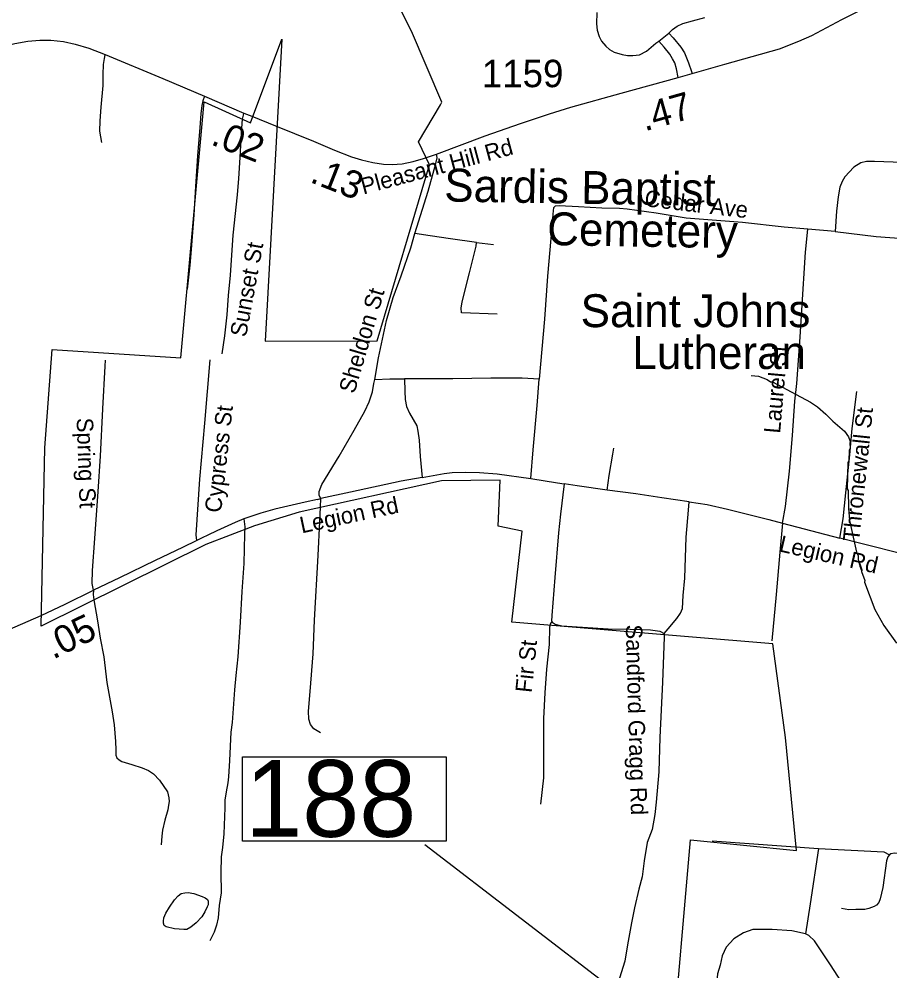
# Model space of a CAD drawing. Extents: x 1159738 to 1321356, y 736314 to 882035.
# Drawn here: x 1254810 to 1258783, y 771364 to 775705 of the extents above; entities that cross this region are included whole.
import ezdxf

# ---------------------------------------------------------------- set-up
doc = ezdxf.new("R2010")
doc.units = 0
for name, color, linetype in [('Exist Boundary Political City Limit New', 7, 'Continuous'), ('Exist Cultural Cemetery Label', 7, 'Continuous'), ('Exist Cultural Church Label', 7, 'Continuous'), ('Exist Hydrographic Misc Water Feature', 7, 'Continuous'), ('Exist Road Non-System Type 51', 7, 'Continuous'), ('Exist Road Non-System Type 51 Label', 7, 'Continuous'), ('Exist Road Secondary Mileage Hundredths English Label', 7, 'Continuous'), ('Exist Road Secondary Structure Standard Bridge Number Label', 7, 'Continuous'), ('Exist Road Secondary Type 51 Attributed', 7, 'Continuous'), ('Exist Road Secondary Type 51 Label', 7, 'Continuous'), ('Exist Road Secondary Type 51 Number Label', 7, 'Continuous'), ('Map Preparation Boundary City Limit Buffer Line', 7, 'Continuous')]:
    doc.layers.add(name, color=color, linetype=linetype)

msp = doc.modelspace()

# ---------------------------------------------------------------- linework, layer by layer
at = {"layer": 'Exist Boundary Political City Limit New'}
msp.add_line((1258356, 771913.3), (1258306.9, 772428.7), dxfattribs=at)
for points in [[(1256599.9, 775650.6), (1256435.6, 775978.4)], [(1254928, 773749.2), (1254960.4, 774198), (1255548.5, 774159.7), (1255654.5, 775328.1), (1255865.9, 775232.8), (1256009.3, 775613.5), (1255932.4, 774237), (1256443.1, 774237.4), (1256682.7, 775040.9), (1256632.8, 775144.8), (1256731.8, 775314.1), (1256738, 775325.9), (1256599.9, 775650.6)], [(1258306.9, 772428.7), (1258249, 772856.6), (1257057.6, 772954.5), (1257104.7, 773369.5), (1256995.9, 773393), (1257004.7, 773602), (1256737.1, 773599), (1256087.2, 773456.8), (1255884.4, 773394.8), (1255661.5, 773309.4), (1254910.4, 772936.9), (1254928, 773749.2)], [(1258748, 769032.9), (1258230, 768945), (1258209.5, 769082.6), (1258189.3, 769147.7), (1258154.9, 769175.3), (1258128.7, 769211), (1257960, 769313.2), (1257938.6, 769347.1), (1257845.4, 769353.7), (1257825.2, 769206.1), (1257207.5, 769215.7), (1257198, 769092), (1256982.3, 769096.7), (1257045.5, 769806.9), (1257710.9, 769757), (1257786.5, 770964.5), (1257872.3, 771962.7), (1258356, 771913.3)]]:
    msp.add_lwpolyline(points, dxfattribs=at)
at = {"layer": 'Exist Hydrographic Misc Water Feature'}
for points in [[(1258149.1, 774079.2), (1258183, 774076.1), (1258222.8, 774061.3), (1258238.4, 774050.3), (1258246.4, 774050.2), (1258420.1, 773958.1), (1258451.6, 773936.9), (1258490.8, 773904.1), (1258522, 773871.5), (1258574.8, 773826.1), (1258594.2, 773799.5), (1258601.6, 773778.8), (1258599.5, 773771.5), (1258600.9, 773746.8), (1258596.7, 773739.5), (1258595.4, 773691.1), (1258591.1, 773683), (1258588.1, 773563.2), (1258591.8, 773554.9), (1258593.8, 773475.3), (1258598.4, 773418.6), (1258630.7, 773274.3), (1258638.3, 773257.8), (1258637.8, 773242.2), (1258645, 773210), (1258652.6, 773193.5), (1258652.3, 773185.3), (1258667.4, 773144.8), (1258667.2, 773137.4), (1258714, 773013.3), (1258754.1, 772940.3), (1258812.1, 772858.7)], [(1255496.1, 771654.9), (1255518.9, 771688.1), (1255535.4, 771707.5), (1255549.6, 771717), (1255565.8, 771720.8), (1255581.9, 771722.1), (1255607.7, 771717.5), (1255645.3, 771704.4), (1255659.2, 771698.4), (1255669, 771690), (1255672.8, 771681.8), (1255672.7, 771676), (1255672.4, 771666.2), (1255668.2, 771656.4), (1255657.6, 771634.4), (1255643, 771610.9), (1255618.3, 771583.5), (1255593.8, 771564.3), (1255575.5, 771554), (1255561.4, 771552.7), (1255519.5, 771556), (1255481.7, 771564.9), (1255471.8, 771570.9), (1255468.2, 771581.6), (1255468.3, 771591.5), (1255470.8, 771607), (1255479.4, 771627.4), (1255496.1, 771654.9)]]:
    msp.add_lwpolyline(points, dxfattribs=at)
at = {"layer": 'Exist Road Non-System Type 51'}
for points in [[(1257446.3, 775735.8), (1257444.6, 775683), (1257446.8, 775655.2), (1257455.7, 775626.2), (1257466.5, 775604.7), (1257486.2, 775581.4), (1257503.7, 775566.1), (1257525.2, 775554.5), (1257561.5, 775543.7), (1257585.7, 775539.7), (1257609.9, 775538.8), (1257640, 775542.8), (1257672.7, 775559.4), (1257715.5, 775595.7), (1257728.9, 775604.7), (1257774.7, 775641), (1257790.8, 775657.2), (1257811.4, 775672.9), (1257838.3, 775685), (1257881.3, 775697.1), (1257938, 775711.8)], [(1257774.7, 775641), (1257793.7, 775619.1), (1257829.1, 775577.8), (1257845.7, 775550.9), (1257863.7, 775505.6), (1257878, 775466.1), (1257881.1, 775456.8)], [(1257817, 775438.9), (1257809, 775478.3), (1257801.8, 775505.2), (1257791.5, 775523.6), (1257778.5, 775545.2), (1257753, 775577.5), (1257728.9, 775604.7)], [(1255187, 775142.5), (1255178.9, 775194.2), (1255179.4, 775241.1), (1255184.5, 775303), (1255193.4, 775401.7), (1255194.3, 775452), (1255194.7, 775498.1), (1255199.4, 775525.2), (1255201.9, 775533.8), (1255203.2, 775544.2)], [(1255655.8, 775353.3), (1255648, 775331.8), (1255643.7, 775311.7), (1255639.4, 775273.8), (1255635.2, 775210.6), (1255624.5, 775081.1), (1255615.6, 774941.8), (1255607, 774812.8), (1255594.7, 774653.8), (1255588.3, 774583.2), (1255576.8, 774473.7)], [(1255737, 774178.1), (1255749, 774260.9), (1255758.7, 774357.1), (1255765.5, 774444.6), (1255774.5, 774536.9), (1255787.3, 774720.2), (1255806.9, 774904.2), (1255813.3, 774977.6), (1255819.2, 775073.6), (1255824.3, 775187.1), (1255829, 775248.3), (1255834.1, 775267.5), (1255835.6, 775276.5)], [(1259246.3, 775164.8), (1259228.8, 775158.9), (1259200.9, 775148.7), (1259111.6, 775107.1), (1259045.5, 775081.9), (1258986.9, 775065.5), (1258938.5, 775055.3), (1258877.2, 775051.2), (1258797.7, 775053.2), (1258711.8, 775056), (1258675.7, 775055.3), (1258649.8, 775049.8), (1258618.4, 775029.4), (1258576.2, 774985.7), (1258564.1, 774964.9), (1258553.9, 774938.3), (1258546.4, 774894), (1258538.9, 774829.2), (1258532.1, 774736.4)], [(1256615.6, 774727), (1256675.6, 774920.3), (1256711.9, 775046.9), (1256717.3, 775071.8), (1256716, 775082.6), (1256713.5, 775089.6)], [(1258408.2, 774747.6), (1258300.7, 774756.4), (1258110.5, 774778.2), (1257852.6, 774797.3), (1257717, 774820.5), (1257584.4, 774838.2), (1257548.3, 774841.6), (1257467.9, 774843), (1257362.2, 774848.4), (1257274.5, 774853.2), (1257255.4, 774851.8), (1257247.9, 774845), (1257245.9, 774832.7), (1257235.6, 774704.5), (1257221.3, 774533.5), (1257206.4, 774336.8), (1257182.2, 774062.9)], [(1258292.3, 773406.1), (1258306.2, 773481.8), (1258323.9, 773644.2), (1258338.1, 773806.8), (1258349, 773963.4), (1258357.2, 774043.2), (1258372.8, 774254), (1258380.3, 774377.5), (1258398, 774642.9), (1258408.2, 774747.6)], [(1258532.1, 774736.4), (1258408.2, 774747.6)], [(1256432.5, 774061.6), (1256449.8, 774160.5), (1256486.8, 774330.1), (1256517.2, 774435.9), (1256553.6, 774534.4), (1256596.7, 774662.2), (1256615.6, 774727)], [(1256897.3, 774687.1), (1256778.6, 774703.3), (1256685.6, 774716.1), (1256615.6, 774727)], [(1258532.1, 774736.4), (1258720.2, 774714.1), (1258928, 774698.5), (1259091.7, 774680)], [(1256991.7, 774360.2), (1256827.9, 774365.6), (1256826.6, 774387.2), (1256831.3, 774416.2), (1256865, 774548.4), (1256894.6, 774670.3), (1256897.3, 774687.1)], [(1256897.3, 774687.1), (1256974.2, 774677)], [(1255149.4, 773100.1), (1255143.4, 773131.3), (1255145.7, 773190.8), (1255155.9, 773336.2), (1255171.3, 773550.1), (1255181, 773711.2), (1255192.1, 773927.4), (1255202.8, 774122.7), (1255203.7, 774150.1)], [(1255621, 773328), (1255618.1, 773353.6), (1255635.2, 773606.5), (1255657.6, 773862.1), (1255681.7, 774150.6)], [(1256186.6, 773518.2), (1256179.1, 773532.4), (1256178.4, 773550.6), (1256191.9, 773582.4), (1256269.5, 773712.6), (1256338.9, 773830.6), (1256388, 773917.2), (1256407.6, 773959.7), (1256421.7, 774005.6), (1256428.5, 774044), (1256432.5, 774061.6)], [(1256432.5, 774061.6), (1256501.7, 774064.7), (1256568.7, 774064.3)], [(1257182.2, 774062.9), (1257104.6, 774066.9), (1256961.7, 774067.6), (1256788.1, 774064.2), (1256568.7, 774064.3)], [(1256568.7, 774064.3), (1256569.4, 774009), (1256571.4, 773969.8), (1256577.5, 773938.8), (1256590.9, 773907.8), (1256624, 773849.7), (1256629.4, 773825.5), (1256634.8, 773785), (1256639.5, 773710.8), (1256649.5, 773615.2)], [(1257143.8, 773609.9), (1257155.9, 773740.1), (1257174.1, 773943.5), (1257182.2, 774062.9)], [(1258554.4, 773338.7), (1258568.7, 773426.7), (1258581.7, 773544), (1258600.1, 773718.2), (1258609.7, 773838.6), (1258630.9, 774006.4)], [(1257492.2, 773557.5), (1257501.5, 773623.3), (1257518.7, 773721), (1257523.4, 773748.9)], [(1256649.5, 773615.2), (1256552.5, 773598.4), (1256322, 773548), (1256186.6, 773518.2)], [(1256649.5, 773615.2), (1256749.1, 773632.8), (1256786.2, 773636.9), (1256846.8, 773638.9), (1256910.2, 773637.5), (1256991.1, 773630.8), (1257143.8, 773609.9)], [(1257143.8, 773609.9), (1257265.7, 773590.6), (1257296, 773586.3)], [(1257296, 773586.3), (1257279.9, 773447.1), (1257270, 773362.3), (1257253.4, 773159.3), (1257240.6, 772984.9), (1257239.5, 772959.8), (1257241.2, 772955.3)], [(1257492.2, 773557.5), (1257355.5, 773576.4), (1257296, 773586.3)], [(1257867.2, 773503.4), (1257742.5, 773522.2), (1257624, 773540.5), (1257492.2, 773557.5)], [(1256170.7, 773514.7), (1256115.5, 773502.2), (1255977.4, 773470.8), (1255912.5, 773452.3), (1255836, 773425.8)], [(1256184.4, 772449.5), (1256154.8, 772468.8), (1256138.9, 772488.1), (1256132.1, 772512), (1256129.9, 772548.3), (1256137.8, 772639.2), (1256151.5, 772810.3), (1256158.3, 772963.7), (1256174.2, 773258.4), (1256182.1, 773414), (1256185.5, 773479.5), (1256186.6, 773518.2)], [(1256170.7, 773514.7), (1256186.6, 773518.2)], [(1257753.3, 772902.6), (1257770.8, 772924.1), (1257811.3, 772971.2), (1257827.9, 772996.1), (1257836.2, 773016.7), (1257840.1, 773077.1), (1257846.7, 773155.8), (1257852.8, 773342.8), (1257864.4, 773465.1), (1257867.2, 773503.4)], [(1257867.2, 773503.4), (1257948.5, 773491.1), (1258041.6, 773469.5), (1258230, 773422.9), (1258292.3, 773406.1)], [(1255836, 773425.8), (1255796.5, 773408.8), (1255712.9, 773371.6), (1255671.1, 773352.1), (1255645.1, 773339.6), (1255621, 773328)], [(1255836, 773425.8), (1255839.4, 773389.5), (1255839.1, 773356.9), (1255834.9, 773222), (1255826.6, 773094.1), (1255819, 772954.6), (1255808.4, 772796.9), (1255798.6, 772711.9), (1255792.6, 772646.4), (1255782.8, 772497.9), (1255776.7, 772453.2), (1255769.5, 772323.9), (1255765, 772250.1), (1255762, 772221.9), (1255754, 772181.4), (1255748.3, 772143.1), (1255748.3, 772108.6), (1255744.6, 771988.9), (1255737.4, 771927.1), (1255732.5, 771885), (1255730.6, 771813), (1255731.3, 771720.8), (1255722.3, 771662.1), (1255718.1, 771607), (1255711.3, 771572.5), (1255700.7, 771541.5), (1255679.5, 771501.1)], [(1258292.3, 773406.1), (1258280.1, 773274.6), (1258263.8, 773081.8), (1258243.3, 772869.5)], [(1258292.3, 773406.1), (1258554.4, 773338.7)], [(1255621, 773328), (1255555.5, 773295), (1255431, 773236), (1255268.6, 773157.6), (1255149.4, 773100.1)], [(1258958.3, 773234.3), (1258848.8, 773263), (1258656.6, 773312.8), (1258554.4, 773338.7)], [(1255149.4, 773100.1), (1255148, 773080.3), (1255151.3, 773056.6), (1255167.1, 772960.8), (1255180.1, 772881.3), (1255196.3, 772797.1), (1255210.7, 772680.4), (1255234.4, 772546.4), (1255243.2, 772486.1), (1255249.7, 772411.3), (1255251.1, 772372.9), (1255251.6, 772348.8), (1255256.2, 772336.2), (1255266.9, 772326.9), (1255279.4, 772319.9), (1255325, 772306.5), (1255372.3, 772290.6), (1255401.1, 772278.1), (1255423.9, 772262.8), (1255450.1, 772234.7), (1255486.8, 772180.9), (1255492.9, 772154.4), (1255494.3, 772137.7), (1255492.4, 772120), (1255488.2, 772099.6), (1255475.2, 772052.6), (1255464.6, 772006.9), (1255460.8, 771979.5), (1255458.1, 771939.5)], [(1257241.2, 772955.3), (1257234.5, 772949.2), (1257229.5, 772932.6), (1257227.9, 772852.7), (1257216.3, 772740.2), (1257209.1, 772632.4), (1257203, 772514.9), (1257202.4, 772344), (1257201.9, 772245.6), (1257188.6, 772124.2)], [(1257241.2, 772955.3), (1257254.8, 772945.3), (1257286.4, 772938.6), (1257379.7, 772932.1), (1257496.6, 772924.8), (1257597.6, 772923.7), (1257690.6, 772919.8), (1257733.3, 772913.7), (1257753.3, 772902.6)], [(1257753.3, 772902.6), (1257752.3, 772885.8), (1257745.6, 772681.2), (1257732.9, 772428.9), (1257729, 772273), (1257716.8, 772133.8), (1257710.7, 772077), (1257698.6, 772009.4), (1257675.3, 771950), (1257660.9, 771866.6), (1257652.6, 771794), (1257637.1, 771737.2), (1257617.7, 771652.3), (1257603.8, 771583.6), (1257586.1, 771482.9), (1257574, 771408.3), (1257541.4, 771307.4), (1257536.4, 771253.3), (1257542.5, 771160.7), (1257554.7, 771021.9)], [(1257971, 771957.7), (1258456.3, 771922.8)], [(1258456.3, 771922.8), (1258418.1, 771669.9), (1258398.1, 771533.6)], [(1258456.3, 771922.8), (1258755.5, 771907.8), (1258780.7, 771894.4)], [(1258780.7, 771894.4), (1258772.5, 771885.3), (1258767, 771866.9), (1258750.4, 771745.1), (1258738.6, 771692.7), (1258732.1, 771676.1), (1258722, 771665), (1258710, 771658.6), (1258686.9, 771648.4), (1258668.5, 771644.7), (1258627, 771643.8), (1258595.7, 771642.9), (1258561.5, 771648.4)], [(1258981.6, 771369.2), (1258941, 771412.6), (1258924.4, 771441.2), (1258909.7, 771467), (1258902.3, 771494.7), (1258899.5, 771524.3), (1258898.6, 771553.8), (1258911.5, 771639.6), (1258942, 771827), (1258943.8, 771860.3), (1258940.2, 771885.2), (1258928.2, 771894.4), (1258879.3, 771896.2), (1258803.7, 771901.8), (1258786.2, 771899), (1258780.7, 771894.4)], [(1258398.1, 771533.6), (1258335, 771546.9), (1258245.2, 771553.5), (1258157.1, 771553.5), (1258113.9, 771538.5), (1258070.7, 771510.3), (1258035.8, 771472), (1258017.5, 771433.8), (1258007.5, 771390.5), (1257995.9, 771350.6), (1257984.3, 771209.2), (1257977.8, 771068.4)], [(1258616, 770968.6), (1258634.3, 771159.9), (1258631, 771189.8), (1258619.3, 771221.4), (1258594.4, 771263), (1258511.3, 771392.7), (1258438.2, 771500.9), (1258413.2, 771525.8), (1258398.1, 771533.6)]]:
    msp.add_lwpolyline(points, dxfattribs=at)
at = {"layer": 'Exist Road Secondary Structure Standard Bridge Number Label'}
msp.add_line((1259434, 769808.6), (1256661.7, 771939.9), dxfattribs=at)
msp.add_lwpolyline([(1255828.6, 772340.3), (1256757.6, 772340.3), (1256757.6, 771956.2), (1255828.6, 771956.2)], close=True, dxfattribs=at)
at = {"layer": 'Exist Road Secondary Type 51 Attributed'}
for points in [[(1258029.1, 775499.5), (1258278.5, 775569.5), (1258367.4, 775604), (1258426.8, 775630.6), (1258562.7, 775702.6), (1258708.9, 775775.7), (1258931.4, 775905.1)], [(1253644.5, 775302.1), (1253700, 775314.7), (1253760.2, 775327.5), (1253934.3, 775372.7), (1254224.5, 775449.8), (1254523.7, 775526.7), (1254690.6, 775569.6), (1254790.9, 775593.4), (1254850.2, 775603.8), (1254904.5, 775609.3), (1254954.6, 775608.7), (1255012.1, 775603.2), (1255065.9, 775590.4), (1255127.7, 775572.6), (1255203.2, 775544.2), (1255465.8, 775434.6), (1255655.8, 775353.3), (1255835.6, 775276.5), (1255872.1, 775262.5)], [(1256655.1, 775068.9), (1256713.5, 775089.6), (1256935.8, 775172.2), (1257096.8, 775229.8), (1257229.2, 775273.6), (1257327.1, 775302.9), (1257556.4, 775366.9), (1257817, 775438.9), (1257881.1, 775456.8), (1258029.1, 775499.5)], [(1255872.1, 775262.5), (1255980.4, 775219)], [(1255980.4, 775219), (1256153.1, 775148.1), (1256248.8, 775108.2), (1256326.3, 775077.8), (1256372.4, 775063), (1256423.4, 775050.5), (1256472.9, 775043.2), (1256511.8, 775041.9), (1256557.1, 775044.8), (1256607.9, 775055.6), (1256655.1, 775068.9)], [(1254911.5, 772985.7), (1255020.4, 773036.7), (1255149.4, 773100.1)], [(1254181.2, 772788.5), (1254270.1, 772790.7), (1254398.2, 772801), (1254461.3, 772807.8), (1254517.4, 772823.3), (1254583.6, 772848.2), (1254696.4, 772892.5), (1254911.5, 772985.7)]]:
    msp.add_lwpolyline(points, dxfattribs=at)
at = {"layer": 'Map Preparation Boundary City Limit Buffer Line'}
msp.add_line((1258356, 771913.3), (1258306.9, 772428.7), dxfattribs=at)
for points in [[(1256599.9, 775650.6), (1256435.6, 775978.4)], [(1254928, 773749.2), (1254960.4, 774198), (1255548.5, 774159.7), (1255654.5, 775328.1), (1255865.9, 775232.8), (1256009.3, 775613.5), (1255932.4, 774237), (1256443.1, 774237.4), (1256682.7, 775040.9), (1256632.8, 775144.8), (1256731.8, 775314.1), (1256738, 775325.9), (1256599.9, 775650.6)], [(1258306.9, 772428.7), (1258249, 772856.6), (1257057.6, 772954.5), (1257104.7, 773369.5), (1256995.9, 773393), (1257004.7, 773602), (1256737.1, 773599), (1256087.2, 773456.8), (1255884.4, 773394.8), (1255661.5, 773309.4), (1254910.4, 772936.9), (1254928, 773749.2)], [(1258748, 769032.9), (1258230, 768945), (1258209.5, 769082.6), (1258189.3, 769147.7), (1258154.9, 769175.3), (1258128.7, 769211), (1257960, 769313.2), (1257938.6, 769347.1), (1257845.4, 769353.7), (1257825.2, 769206.1), (1257207.5, 769215.7), (1257198, 769092), (1256982.3, 769096.7), (1257045.5, 769806.9), (1257710.9, 769757), (1257786.5, 770964.5), (1257872.3, 771962.7), (1258356, 771913.3)]]:
    msp.add_lwpolyline(points, dxfattribs=at)

# ---------------------------------------------------------------- texts
at = {"layer": 'Exist Cultural Cemetery Label'}
for s, p in [('Sardis Baptist', (1256748.9, 774873.6)), ('Cemetery', (1257218.3, 774674.7))]:
    msp.add_text(s, height=150, rotation=359.0363, dxfattribs=at).set_placement(p)
at = {"layer": 'Exist Cultural Church Label'}
for s, p in [('Saint Johns', (1257371.7, 774300.3)), ('Lutheran', (1257608, 774109.3))]:
    msp.add_text(s, height=150, dxfattribs=at).set_placement(p)
at = {"layer": 'Exist Road Non-System Type 51 Label'}
for s, rotation, p in [('Cedar Ave', 353.2835, (1257660.2, 774852.2)), ('Sunset St', 79.5261, (1255845.5, 774252)), ('Sheldon St', 73.5944, (1256339.5, 773993.6)), ('Laurel St', 84.989, (1258281.5, 773813.5)), ('Cypress St', 83.6329, (1255731.2, 773451.4)), ('Thronewall St', 84.032, (1258642.2, 773320.2)), ('Spring St', 271.9476, (1255072.5, 773885.9)), ('Legion Rd', 12.0472, (1256099.5, 773359.7)), ('Legion Rd', 347.0579, (1258272.8, 773278.6)), ('Sandford Gragg Rd', 271.5862, (1257577.5, 772943.3)), ('Fir St', 83.9339, (1257147.9, 772630.7))]:
    msp.add_text(s, height=75, rotation=rotation, dxfattribs=at).set_placement(p)
at = {"layer": 'Exist Road Secondary Mileage Hundredths English Label'}
for s, rotation, p in [('.47', 15.6773, (1257664.1, 775192.8)), ('.02', 338.1323, (1255680.1, 775135.2)), ('.13', 338.6337, (1256132.1, 774963.1)), ('.05', 26.1798, (1254965, 772783.6))]:
    msp.add_text(s, height=125, rotation=rotation, dxfattribs=at).set_placement(p)
at = {"layer": 'Exist Road Secondary Structure Standard Bridge Number Label'}
msp.add_text('188', height=350, dxfattribs=at).set_placement((1255841.2, 771976))
at = {"layer": 'Exist Road Secondary Type 51 Label'}
msp.add_text('Pleasant Hill Rd', height=75, rotation=15.0445, dxfattribs=at).set_placement((1256380.6, 774904.6))
at = {"layer": 'Exist Road Secondary Type 51 Number Label'}
msp.add_text('1159', height=125, dxfattribs=at).set_placement((1256921.3, 775394.7))

doc.saveas('drawing.dxf')
